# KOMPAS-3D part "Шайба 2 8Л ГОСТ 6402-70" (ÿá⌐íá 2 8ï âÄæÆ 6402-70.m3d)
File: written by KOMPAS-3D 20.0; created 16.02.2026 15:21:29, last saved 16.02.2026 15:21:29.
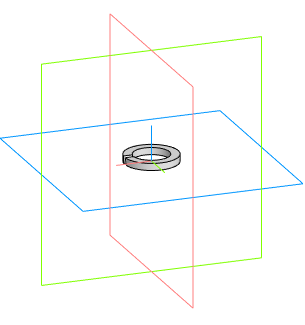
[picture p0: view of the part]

Document properties: Автор: admin; Полное имя файла: P:\INSTART\Технический отдел\ОР\Прочие задачи\КД на номенклатурный ряд\КД на типоразмеры дросселей\Сетевые дроссели ISF\ISF-4\Тип 1\ISF-132_256-4\0723\Новая папка\Шайба 2 8Л ГОСТ 6402-70.m3d

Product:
- Part/product: Шайба 2 8Л ГОСТ 6402-70

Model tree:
1. Операция без истории:1  (labels: Шайба 2 8Л ГОСТ 6402-70)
